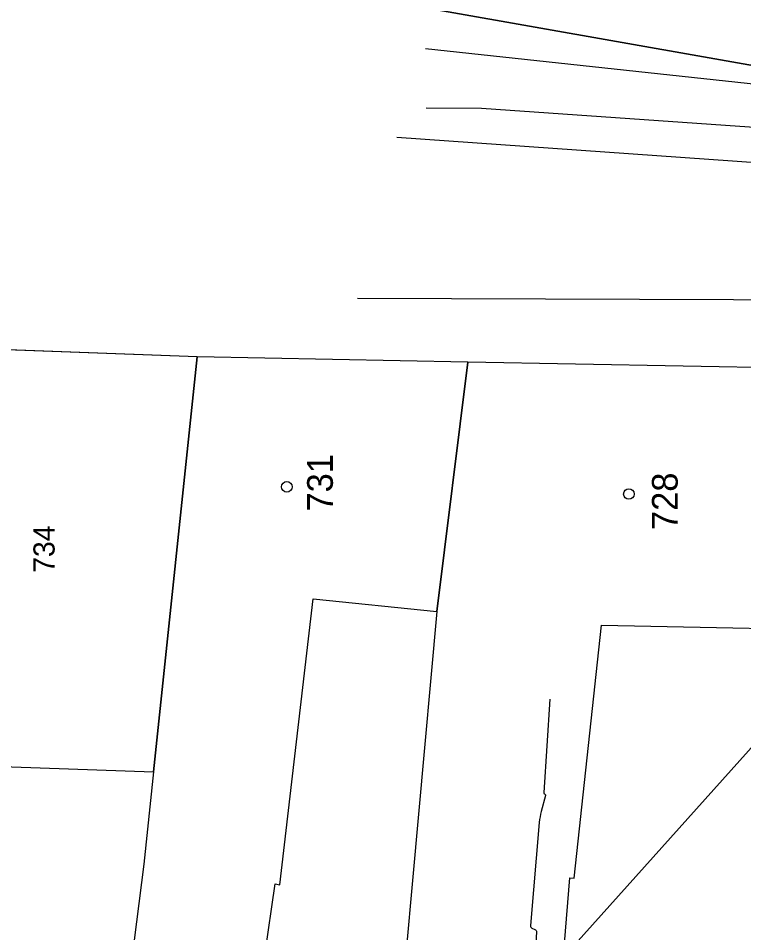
# Model space of a CAD drawing. Extents: x -534481 to -534262, y -1190577 to -1190138.
# Drawn here: x -534379.97 to -534356, y -1190282.16 to -1190251.94 of the extents above; entities that cross this region are included whole.
import ezdxf

# ---------------------------------------------------------------- set-up
doc = ezdxf.new("R2010")
doc.units = 0
for name, color, linetype in [('14', 7, 'Continuous'), ('Definiční body', 7, 'Continuous'), ('Polygon budovy', 7, 'Continuous'), ('Polygon parcely', 7, 'Continuous'), ('Vrstva 1', 7, 'Continuous'), ('Vrstva 19', 7, 'Continuous'), ('Vrstva 30', 7, 'Continuous'), ('Vrstva 31', 7, 'Continuous'), ('Vrstva 35', 7, 'Continuous'), ('Vrstva 46', 7, 'Continuous')]:
    doc.layers.add(name, color=color, linetype=linetype)

msp = doc.modelspace()

# ---------------------------------------------------------------- linework, layer by layer
at = {"layer": '14'}
msp.add_lwpolyline([(-534366.512, -1190252.942), (-534352.92, -1190254.4), (-534352.18, -1190261.35), (-534348.055, -1190261.165), (-534339.72, -1190262.169), (-534334.017, -1190262.845)], dxfattribs=at)
at = {"layer": 'Definiční body'}
for p, q in [((-534374.06, -1190263.13), (-534382.71, -1190262.81)), ((-534365.11, -1190263.3), (-534374.06, -1190263.13))]:
    msp.add_line(p, q, dxfattribs=at)
for points in [[(-534374.06, -1190263.13), (-534375.5, -1190276.84), (-534375.82, -1190279.89), (-534376.96, -1190288.9), (-534377.73, -1190294.18), (-534378.22, -1190297.6), (-534378.27, -1190297.93), (-534378.86, -1190300.97), (-534380.33, -1190300.65), (-534380.94, -1190304.74), (-534381.36, -1190307.53), (-534381.75, -1190310.15)], [(-534365.11, -1190263.3), (-534366.14, -1190271.54), (-534367.96, -1190291.63), (-534368.98, -1190298.28), (-534369.63, -1190302.5), (-534370.75, -1190309.73)], [(-534347.63, -1190264.06), (-534347.63, -1190263.6), (-534350.88, -1190263.57), (-534365.11, -1190263.3)]]:
    msp.add_lwpolyline(points, dxfattribs=at)
at = {"layer": 'Polygon parcely'}
for points in [[(-534382.71, -1190262.81), (-534383.47, -1190268.46), (-534384.56, -1190276.52), (-534375.5, -1190276.84), (-534374.06, -1190263.13)], [(-534377.73, -1190294.18), (-534373.53, -1190294.69), (-534371.48, -1190280.54), (-534371.33, -1190280.57), (-534370.23, -1190271.12), (-534366.14, -1190271.54), (-534365.11, -1190263.3), (-534374.06, -1190263.13), (-534375.5, -1190276.84), (-534375.82, -1190279.89), (-534376.96, -1190288.9)], [(-534366.14, -1190271.54), (-534367.96, -1190291.63), (-534363.08, -1190291.98), (-534362.74, -1190289.52), (-534362.49, -1190289.56), (-534361.74, -1190280.34), (-534361.6, -1190280.35), (-534360.7, -1190271.99), (-534350.93, -1190272.19), (-534350.88, -1190263.57), (-534365.11, -1190263.3)]]:
    msp.add_lwpolyline(points, close=True, dxfattribs=at)
at = {"layer": 'Vrstva 1'}
for points in [[(-534366.49, -1190254.906), (-534364.66, -1190254.91), (-534354.86, -1190255.6)], [(-534333.902, -1190262.197), (-534340.815, -1190261.304), (-534368.758, -1190261.205)]]:
    msp.add_lwpolyline(points, dxfattribs=at)
at = {"layer": 'Vrstva 19'}
msp.add_lwpolyline([(-534362.402, -1190274.445), (-534362.608, -1190277.526), (-534362.608, -1190277.536), (-534362.605, -1190277.546), (-534362.6, -1190277.554), (-534362.593, -1190277.562), (-534362.558, -1190277.59), (-534362.551, -1190277.597), (-534362.547, -1190277.606), (-534362.545, -1190277.615), (-534362.547, -1190277.625), (-534362.688, -1190278.147), (-534362.711, -1190278.238), (-534362.729, -1190278.33), (-534362.743, -1190278.422), (-534362.753, -1190278.515), (-534363.047, -1190281.921), (-534363.046, -1190281.947), (-534363.038, -1190281.97), (-534363.023, -1190281.988), (-534363, -1190282.002), (-534362.897, -1190282.05), (-534362.875, -1190282.065), (-534362.859, -1190282.083), (-534362.851, -1190282.105), (-534362.849, -1190282.132), (-534363.008, -1190284.876)], dxfattribs=at)
at = {"layer": 'Vrstva 30'}
for points in [[(-534261.668, -1190163.461), (-534407.912, -1190137.674), (-534426.145, -1190241.079), (-534279.901, -1190266.866)], [(-534279.901, -1190266.866), (-534426.145, -1190241.079), (-534444.378, -1190344.484), (-534298.134, -1190370.27)]]:
    msp.add_lwpolyline(points, dxfattribs=at)
at = {"layer": 'Vrstva 31'}
msp.add_lwpolyline([(-534409.732, -1190388.64), (-534397.101, -1190322.153), (-534346.296, -1190265.502)], dxfattribs=at)
at = {"layer": 'Vrstva 35'}
msp.add_lwpolyline([(-534367.462, -1190255.872), (-534340.907, -1190257.743), (-534313.909, -1190261.752)], dxfattribs=at)
at = {"layer": 'Vrstva 46'}
for centre in [(-534371.095, -1190267.424), (-534359.793, -1190267.662)]:
    msp.add_circle(centre, 0.175, dxfattribs=at)

# ---------------------------------------------------------------- texts
at = {"layer": 'Polygon budovy'}
for s, height, p in [('731', 0.85, (-534369.574, -1190268.24)), ('728', 0.85, (-534358.181, -1190268.85)), ('734', 0.7, (-534378.768, -1190270.265))]:
    msp.add_text(s, height=height, rotation=90, dxfattribs=at).set_placement(p)

doc.saveas('drawing.dxf')
